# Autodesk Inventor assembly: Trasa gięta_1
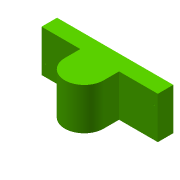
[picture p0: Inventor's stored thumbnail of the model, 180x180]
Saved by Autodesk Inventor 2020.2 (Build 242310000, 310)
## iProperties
Created: 2014-08
Part Number: Trasa gięta_1
Document SubType Name: Assembly
Designer: F.Stasiak
Catalog Web Link: www.expertbooks.pl
Manager: www.cadconsulting.pl
Company: Fabian Stasiak CAD Consulting
Author: F.Stasiak
Subject: Zbiór ćwiczeń. Autodesk Inventor 2020. Kurs Professional
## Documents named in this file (2)
- C:\2020_Kurs_Professional\R1 Rury\Trasa gięta_1.iam
- C:\2020_Kurs_Professional\R1 Rury\Konstrukcja_gięta_1.ipt
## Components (1 placed, 1 different names)
1. Konstrukcja_gięta_1:1
